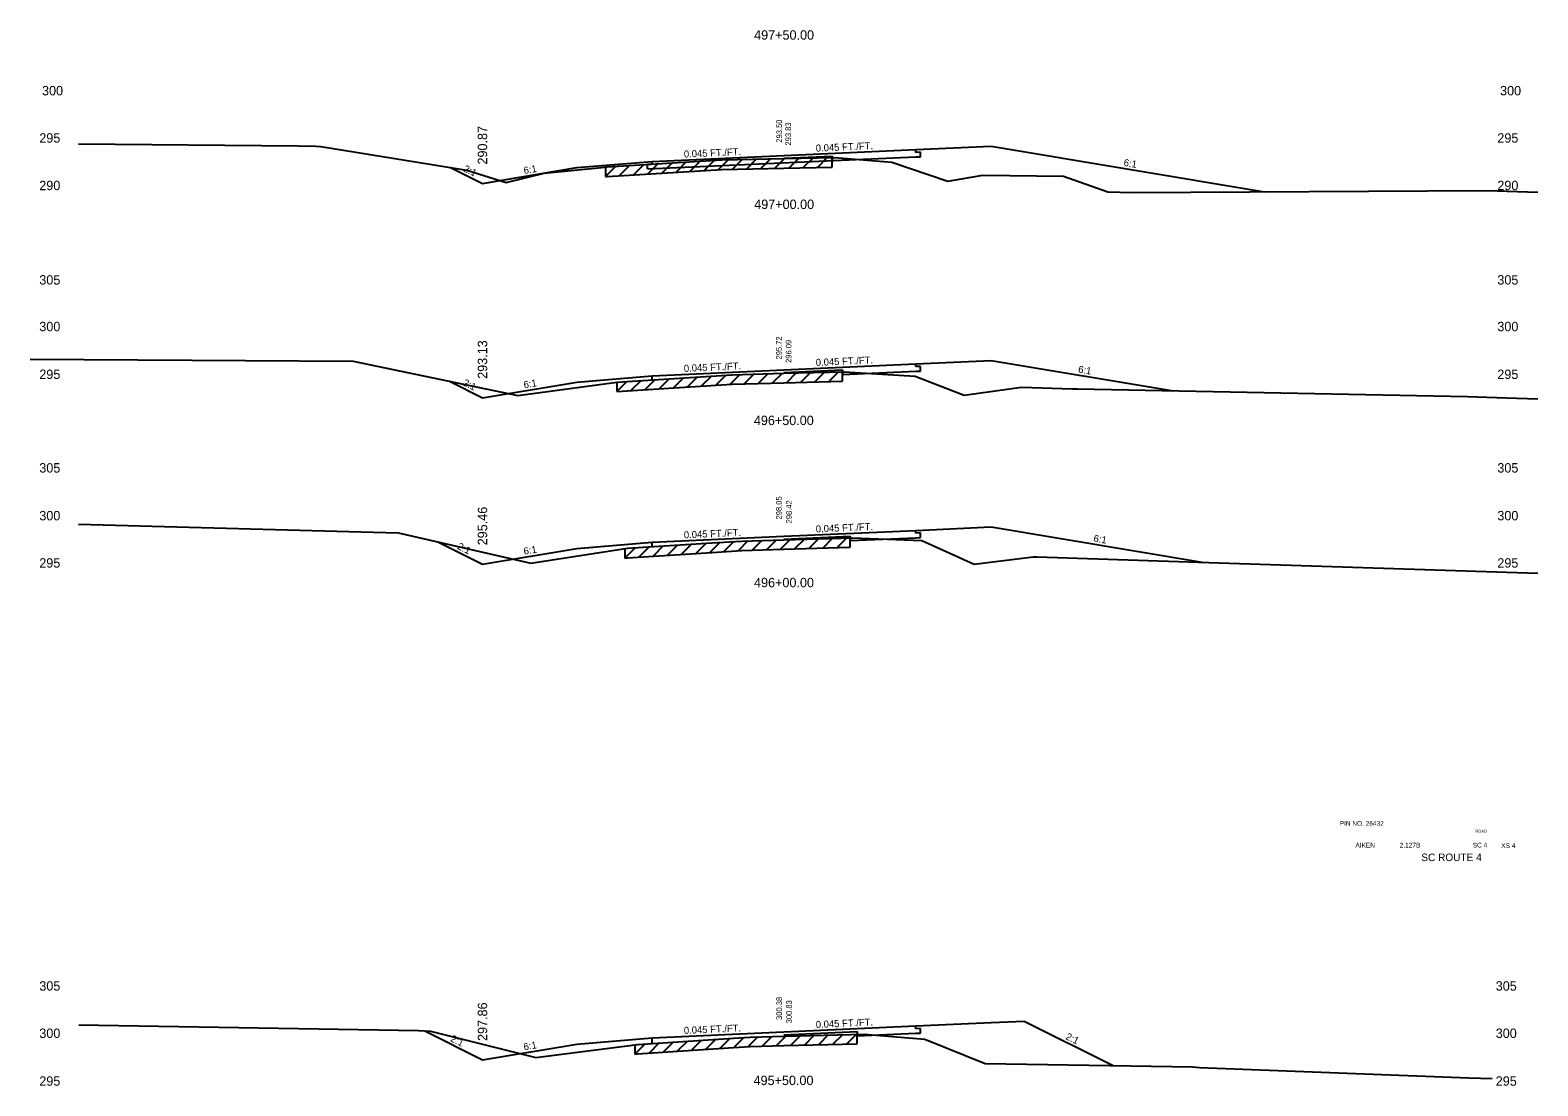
# Model space of a CAD drawing. Extents: x 883 to 1160, y 1002 to 4323.
# Drawn here: x 1000 to 1160, y 1420.1 to 1532.1 of the extents above; entities that cross this region are included whole.
import ezdxf

# ---------------------------------------------------------------- set-up
doc = ezdxf.new("R2010")
doc.units = 0
for name, color, linetype in [('Level 1', 7, 'Continuous'), ('Level 10', 7, 'Continuous'), ('Level 11', 7, 'Continuous'), ('Level 12', 7, 'Continuous'), ('Level 3', 7, 'Continuous'), ('Level 32', 7, 'Continuous'), ('Level 33', 7, 'Continuous'), ('Level 53', 7, 'Continuous'), ('Level 59', 7, 'Continuous'), ('Level 6', 7, 'Continuous'), ('Level 60', 7, 'Continuous'), ('Level 61', 7, 'Continuous'), ('Level 7', 7, 'Continuous')]:
    doc.layers.add(name, color=color, linetype=linetype)

msp = doc.modelspace()

# ---------------------------------------------------------------- linework, layer by layer
at = {"layer": 'Level 11'}
for p, q in [((1094, 1519.16), (1094, 1519.46)), ((1094.5, 1519.18), (1094, 1519.16)), ((1094, 1518.68), (1094.5, 1518.7)), ((1094.5, 1518.7), (1094.5, 1519.18)), ((1066, 1517.9), (1065.5, 1517.88)), ((1065.5, 1517.4), (1065.5, 1517.88)), ((1066, 1517.9), (1066, 1518.2)), ((1094, 1496.42), (1094, 1496.72)), ((1094.5, 1496.44), (1094, 1496.42)), ((1094.5, 1495.96), (1094.5, 1496.44)), ((1066, 1495.02), (1066, 1495.46)), ((1094, 1495.94), (1094.5, 1495.96)), ((1094, 1478.75), (1094, 1479.05)), ((1094.5, 1478.77), (1094, 1478.75)), ((1094.5, 1478.29), (1094.5, 1478.77)), ((1066, 1477.31), (1066, 1477.79)), ((1094, 1478.27), (1094.5, 1478.29)), ((1094, 1426.16), (1094, 1426.46)), ((1094.5, 1426.18), (1094, 1426.16)), ((1094, 1425.68), (1094.5, 1425.7)), ((1094.5, 1425.7), (1094.5, 1426.18)), ((1066, 1424.6), (1066, 1425.2))]:
    msp.add_line(p, q, dxfattribs=at)
at = {"layer": 'Level 12'}
for p, q in [((1065.5, 1517.4), (1094, 1518.68)), ((1085.11, 1518.6), (1085.11, 1518.28)), ((1086.22, 1495.59), (1094, 1495.94)), ((1086.22, 1495.87), (1086.22, 1495.59)), ((1087.03, 1477.96), (1094, 1478.27)), ((1087.03, 1478.26), (1087.03, 1477.96)), ((1087.76, 1425.4), (1094, 1425.68)), ((1087.76, 1425.57), (1087.76, 1425.4))]:
    msp.add_line(p, q, dxfattribs=at)
at = {"layer": 'Level 53'}
for p, q in [((1080, 1518.53), (1085.11, 1518.76)), ((1085.11, 1518.76), (1085.11, 1518.6)), ((1080, 1495.79), (1086.22, 1496.07)), ((1086.22, 1496.07), (1086.22, 1495.87)), ((1080, 1478.12), (1087.03, 1478.44)), ((1087.03, 1478.44), (1087.03, 1478.26)), ((1080, 1425.53), (1087.76, 1425.88)), ((1087.76, 1425.88), (1087.76, 1425.57))]:
    msp.add_line(p, q, dxfattribs=at)
at = {"layer": 'Level 59'}
for p, q in [((1066, 1518.2), (1080, 1518.83)), ((1080, 1518.83), (1094, 1519.46)), ((1066, 1495.46), (1080, 1496.09)), ((1080, 1496.09), (1094, 1496.72)), ((1066, 1477.79), (1080, 1478.42)), ((1080, 1478.42), (1094, 1479.05)), ((1066, 1425.2), (1080, 1425.83)), ((1080, 1425.83), (1094, 1426.46))]:
    msp.add_line(p, q, dxfattribs=at)
at = {"layer": 'Level 6'}
for p, q in [((1094, 1519.46), (1102, 1519.82)), ((1058, 1517.54), (1066, 1518.2)), ((1094, 1496.72), (1102, 1497.08)), ((1058, 1494.79), (1066, 1495.46)), ((1094, 1479.05), (1102, 1479.41)), ((1058, 1477.13), (1066, 1477.79)), ((1094, 1426.46), (1102, 1426.82)), ((1102, 1426.82), (1105.5, 1426.98)), ((1058, 1424.53), (1066, 1425.2))]:
    msp.add_line(p, q, dxfattribs=at)
at = {"layer": 'Level 60'}
for p, q in [((1005.12, 1520.05), (1028.45, 1519.85)), ((1028.45, 1519.85), (1030.31, 1519.82)), ((1030.31, 1519.82), (1030.85, 1519.79)), ((1030.85, 1519.79), (1046.34, 1517.28)), ((1073.41, 1518.36), (1080, 1518.5)), ((1080, 1518.5), (1085.41, 1518.61)), ((1085.41, 1518.61), (1091.43, 1518.13)), ((1046.34, 1517.28), (1050.5, 1515.97)), ((1050.5, 1515.97), (1054.55, 1516.97)), ((1054.55, 1516.97), (1060.63, 1517.56)), ((1060.63, 1517.56), (1061.22, 1517.61)), ((1061.22, 1517.61), (1073.41, 1518.36)), ((1091.43, 1518.13), (1097.38, 1516.09)), ((1097.38, 1516.09), (1101.11, 1516.75)), ((1101.11, 1516.75), (1109.65, 1516.65)), ((1109.65, 1516.65), (1114.37, 1514.97)), ((1114.37, 1514.97), (1116.86, 1514.92)), ((1116.86, 1514.92), (1154.57, 1515.11)), ((1154.57, 1515.11), (1160, 1514.95)), ((1000, 1497.23), (1034.29, 1497.02)), ((1034.29, 1497.02), (1051.75, 1493.36)), ((1051.75, 1493.36), (1062.25, 1494.78)), ((1062.25, 1494.78), (1070, 1495.28)), ((1070, 1495.28), (1074.49, 1495.57)), ((1074.49, 1495.57), (1080, 1495.72)), ((1080, 1495.72), (1086.39, 1495.87)), ((1086.39, 1495.87), (1093.91, 1495.4)), ((1093.91, 1495.4), (1099.11, 1493.41)), ((1099.11, 1493.41), (1105.19, 1494.24)), ((1105.19, 1494.24), (1110.63, 1494.07)), ((1110.63, 1494.07), (1111.14, 1494.06)), ((1111.14, 1494.06), (1152.53, 1493.25)), ((1152.53, 1493.25), (1156.68, 1493.11)), ((1156.68, 1493.11), (1160, 1493.01)), ((1005.13, 1479.69), (1039.04, 1478.77)), ((1039.04, 1478.77), (1039.37, 1478.7)), ((1039.37, 1478.7), (1053.14, 1475.56)), ((1053.14, 1475.56), (1063.39, 1477.15)), ((1063.39, 1477.15), (1072.35, 1477.71)), ((1072.35, 1477.71), (1075.49, 1477.91)), ((1075.49, 1477.91), (1080, 1478.05)), ((1080, 1478.05), (1087.26, 1478.27)), ((1087.26, 1478.27), (1094.63, 1477.97)), ((1094.63, 1477.97), (1100.19, 1475.46)), ((1100.19, 1475.46), (1106.45, 1476.24)), ((1106.45, 1476.24), (1106.88, 1476.24)), ((1106.88, 1476.24), (1121.86, 1475.74)), ((1121.86, 1475.74), (1122.89, 1475.7)), ((1122.89, 1475.7), (1160, 1474.51)), ((1005.15, 1426.56), (1041.2, 1425.97)), ((1041.2, 1425.97), (1042.47, 1425.89)), ((1042.47, 1425.89), (1053.66, 1423.09)), ((1053.66, 1423.09), (1064.45, 1424.5)), ((1064.45, 1424.5), (1074.63, 1425.17)), ((1074.63, 1425.17), (1076.41, 1425.28)), ((1076.41, 1425.28), (1080, 1425.38)), ((1080, 1425.38), (1088.51, 1425.59)), ((1088.51, 1425.59), (1094.95, 1425.07)), ((1094.95, 1425.07), (1101.35, 1422.46)), ((1101.35, 1422.46), (1123.38, 1422.13)), ((1123.38, 1422.13), (1124.1, 1422.06)), ((1124.1, 1422.06), (1152.66, 1420.95)), ((1152.66, 1420.95), (1155.16, 1420.89))]:
    msp.add_line(p, q, dxfattribs=at)
at = {"layer": 'Level 61'}
for p, q in [((1075.56, 1518.4), (1074.54, 1517.38)), ((1077.06, 1518.44), (1076.04, 1517.42)), ((1078.56, 1518.47), (1077.54, 1517.45)), ((1080.06, 1518.5), (1079.04, 1517.48)), ((1081.56, 1518.53), (1080.54, 1517.51)), ((1083.06, 1518.56), (1082.04, 1517.54)), ((1084.56, 1518.59), (1083.54, 1517.57)), ((1085.11, 1517.6), (1085.11, 1518.6)), ((1062.11, 1517.67), (1061.04, 1516.6)), ((1061.04, 1517.6), (1061.04, 1516.6)), ((1061.22, 1516.61), (1073.41, 1517.36)), ((1063.6, 1517.76), (1062.54, 1516.69)), ((1065.1, 1517.85), (1064.04, 1516.79)), ((1066.6, 1517.94), (1065.54, 1516.88)), ((1068.1, 1518.03), (1067.04, 1516.97)), ((1069.6, 1518.12), (1068.54, 1517.06)), ((1071.1, 1518.22), (1070.04, 1517.15)), ((1072.6, 1518.31), (1071.54, 1517.24)), ((1074.08, 1518.37), (1073.04, 1517.33)), ((1073.41, 1517.36), (1080, 1517.5)), ((1080, 1517.5), (1085.11, 1517.6)), ((1061.04, 1516.6), (1061.22, 1516.61)), ((1063.33, 1494.85), (1062.26, 1493.78)), ((1062.26, 1494.78), (1062.26, 1493.78)), ((1064.83, 1494.95), (1063.76, 1493.88)), ((1066.33, 1495.05), (1065.26, 1493.98)), ((1067.83, 1495.14), (1066.76, 1494.07)), ((1069.33, 1495.24), (1068.26, 1494.17)), ((1070.83, 1495.34), (1069.76, 1494.27)), ((1070, 1494.28), (1074.49, 1494.57)), ((1072.33, 1495.43), (1071.26, 1494.37)), ((1073.84, 1495.53), (1072.77, 1494.46)), ((1075.3, 1495.6), (1074.27, 1494.56)), ((1074.49, 1494.57), (1080, 1494.72)), ((1076.79, 1495.63), (1075.77, 1494.61)), ((1078.29, 1495.67), (1077.27, 1494.65)), ((1079.8, 1495.71), (1078.77, 1494.69)), ((1080, 1494.72), (1086.22, 1494.87)), ((1081.3, 1495.75), (1080.27, 1494.72)), ((1082.8, 1495.79), (1081.77, 1494.76)), ((1084.3, 1495.82), (1083.27, 1494.8)), ((1085.8, 1495.86), (1084.77, 1494.83)), ((1086.22, 1494.87), (1086.22, 1495.87)), ((1062.26, 1493.78), (1070, 1494.28)), ((1064.22, 1477.2), (1063.12, 1476.11)), ((1063.12, 1477.11), (1063.12, 1476.11)), ((1065.69, 1477.3), (1064.62, 1476.23)), ((1067.19, 1477.39), (1066.12, 1476.32)), ((1068.69, 1477.48), (1067.62, 1476.42)), ((1070.19, 1477.58), (1069.12, 1476.51)), ((1071.69, 1477.67), (1070.63, 1476.6)), ((1073.19, 1477.76), (1072.13, 1476.7)), ((1072.35, 1476.71), (1075.49, 1476.91)), ((1074.69, 1477.86), (1073.63, 1476.79)), ((1076.17, 1477.93), (1075.13, 1476.89)), ((1075.49, 1476.91), (1080, 1477.05)), ((1077.66, 1477.98), (1076.63, 1476.94)), ((1079.16, 1478.02), (1078.13, 1476.99)), ((1080.66, 1478.07), (1079.63, 1477.04)), ((1080, 1477.05), (1087.03, 1477.26)), ((1082.16, 1478.11), (1081.13, 1477.08)), ((1083.66, 1478.16), (1082.63, 1477.13)), ((1085.16, 1478.21), (1084.13, 1477.17)), ((1086.66, 1478.25), (1085.63, 1477.22)), ((1087.03, 1477.26), (1087.03, 1478.26)), ((1063.12, 1476.11), (1063.39, 1476.15)), ((1063.39, 1476.15), (1072.35, 1476.71)), ((1065.27, 1424.55), (1064.18, 1423.46)), ((1064.18, 1424.46), (1064.18, 1423.46)), ((1064.45, 1423.5), (1074.63, 1424.17)), ((1066.75, 1424.65), (1065.68, 1423.58)), ((1068.25, 1424.75), (1067.18, 1423.68)), ((1069.75, 1424.85), (1068.68, 1423.78)), ((1071.25, 1424.95), (1070.18, 1423.87)), ((1072.75, 1425.04), (1071.68, 1423.97)), ((1074.25, 1425.14), (1073.18, 1424.07)), ((1074.63, 1424.17), (1076.41, 1424.28)), ((1075.75, 1425.24), (1074.68, 1424.17)), ((1077.21, 1425.31), (1076.18, 1424.27)), ((1076.41, 1424.28), (1080, 1424.38)), ((1078.71, 1425.34), (1077.68, 1424.32)), ((1080.21, 1425.38), (1079.18, 1424.36)), ((1080, 1424.38), (1087.76, 1424.57)), ((1081.7, 1425.42), (1080.68, 1424.39)), ((1083.2, 1425.46), (1082.18, 1424.43)), ((1084.7, 1425.5), (1083.68, 1424.47)), ((1086.2, 1425.53), (1085.18, 1424.51)), ((1087.71, 1425.57), (1086.68, 1424.54)), ((1087.76, 1424.57), (1087.76, 1425.57)), ((1064.18, 1423.46), (1064.45, 1423.5))]:
    msp.add_line(p, q, dxfattribs=at)
at = {"layer": 'Level 7'}
for p, q in [((1102, 1519.82), (1130.99, 1514.99)), ((1044.62, 1517.56), (1048, 1515.87)), ((1048, 1515.87), (1058, 1517.54)), ((1102, 1497.08), (1121.33, 1493.86)), ((1044.49, 1494.88), (1048, 1493.13)), ((1048, 1493.13), (1058, 1494.79)), ((1102, 1479.41), (1124.58, 1475.65)), ((1043.32, 1477.8), (1048, 1475.46)), ((1048, 1475.46), (1058, 1477.13)), ((1041.87, 1425.93), (1048, 1422.86)), ((1105.5, 1426.98), (1114.94, 1422.26)), ((1048, 1422.86), (1058, 1424.53))]:
    msp.add_line(p, q, dxfattribs=at)

# ---------------------------------------------------------------- texts
at = {"layer": 'Level 1'}
for s, height, p in [('497+50.00', 1, (1076.83, 1531.12)), ('497+00.00', 1, (1076.84, 1513.15)), ('496+50.00', 1, (1076.8, 1490.22)), ('496+00.00', 1, (1076.82, 1473.01)), ('PIN NO. 26432', 0.5, (1138.97, 1447.7)), ('AIKEN', 0.5, (1140.64, 1445.39)), (' 2.127B', 0.5, (1145.15, 1445.39)), ('SC 4', 0.5, (1153.09, 1445.39)), ('XS 4', 0.5, (1156.12, 1445.35)), ('SC ROUTE 4', 0.8, (1147.63, 1443.95)), ('495+50.00', 1, (1076.77, 1420.18))]:
    msp.add_text(s, height=height, dxfattribs=at).set_placement(p)
at = {"layer": 'Level 10'}
for s, p in [('293.50', (1079.79, 1520.19)), ('295.72', (1079.76, 1497.18)), ('298.05', (1079.76, 1480.2)), ('300.38', (1079.79, 1427.09))]:
    msp.add_text(s, height=0.6, rotation=90, dxfattribs=at).set_placement(p)
at = {"layer": 'Level 3'}
for s, height, p in [(' 300', 1, (1000.89, 1525.21)), (' 300', 1, (1155.62, 1525.21)), (' 295', 1, (1000.6, 1520.19)), (' 295', 1, (1155.33, 1520.19)), (' 290', 1, (1000.6, 1515.15)), (' 290', 1, (1155.33, 1515.15)), (' 305', 1, (1000.6, 1505.13)), (' 305', 1, (1155.33, 1505.13)), (' 300', 1, (1000.6, 1500.18)), (' 300', 1, (1155.33, 1500.18)), (' 295', 1, (1000.6, 1495.11)), (' 295', 1, (1155.33, 1495.11)), (' 305', 1, (1000.6, 1485.18)), (' 305', 1, (1155.33, 1485.18)), (' 300', 1, (1000.6, 1480.11)), (' 300', 1, (1155.33, 1480.11)), (' 295', 1, (1000.6, 1475.09)), (' 295', 1, (1155.33, 1475.09)), ('ROAD', 0.3, (1153.38, 1446.98)), (' 305', 1, (1000.6, 1430.2)), (' 305', 1, (1155.16, 1430.2)), (' 300', 1, (1000.6, 1425.18)), (' 300', 1, (1155.16, 1425.18)), (' 295', 1, (1000.6, 1420.11)), (' 295', 1, (1155.16, 1420.11))]:
    msp.add_text(s, height=height, dxfattribs=at).set_placement(p)
at = {"layer": 'Level 32'}
for s, rotation, p in [('0.045 FT./FT.', 2.5766, (1083.39, 1519.23)), ('0.045 FT./FT.', 2.5766, (1069.39, 1518.6)), ('6:1', 350.5377, (1116.01, 1517.74)), ('2:1', 333.435, (1045.91, 1517.19)), ('6:1', 9.4623, (1052.43, 1516.86)), ('0.045 FT./FT.', 2.5766, (1069.39, 1495.86)), ('0.045 FT./FT.', 2.5766, (1083.39, 1496.49)), ('6:1', 350.5377, (1111.18, 1495.8)), ('2:1', 333.435, (1045.85, 1494.48)), ('6:1', 9.4623, (1052.43, 1494.12)), ('0.045 FT./FT.', 2.5766, (1069.39, 1478.19)), ('0.045 FT./FT.', 2.5766, (1083.39, 1478.82)), ('6:1', 350.5377, (1112.81, 1477.86)), ('2:1', 333.435, (1045.27, 1477.11)), ('6:1', 9.4623, (1052.43, 1476.45)), ('0.045 FT./FT.', 2.5766, (1083.39, 1426.23)), ('0.045 FT./FT.', 2.5766, (1069.39, 1425.6)), ('2:1', 333.435, (1109.82, 1425.09)), ('2:1', 333.435, (1044.54, 1424.87)), ('6:1', 9.4623, (1052.43, 1423.86))]:
    msp.add_text(s, height=0.75, rotation=rotation, dxfattribs=at).set_placement(p)
at = {"layer": 'Level 33'}
for s, p in [('290.87', (1048.5, 1517.87)), ('293.13', (1048.5, 1495.13)), ('295.46', (1048.5, 1477.46)), ('297.86', (1048.5, 1424.86))]:
    msp.add_text(s, height=1, rotation=90, dxfattribs=at).set_placement(p)
at = {"layer": 'Level 59'}
for s, p in [(' 293.83', (1080.75, 1519.66)), (' 296.09', (1080.79, 1496.59)), (' 298.42', (1080.83, 1479.56)), (' 300.83', (1080.83, 1426.51))]:
    msp.add_text(s, height=0.6, rotation=90, dxfattribs=at).set_placement(p)

doc.saveas('drawing.dxf')
